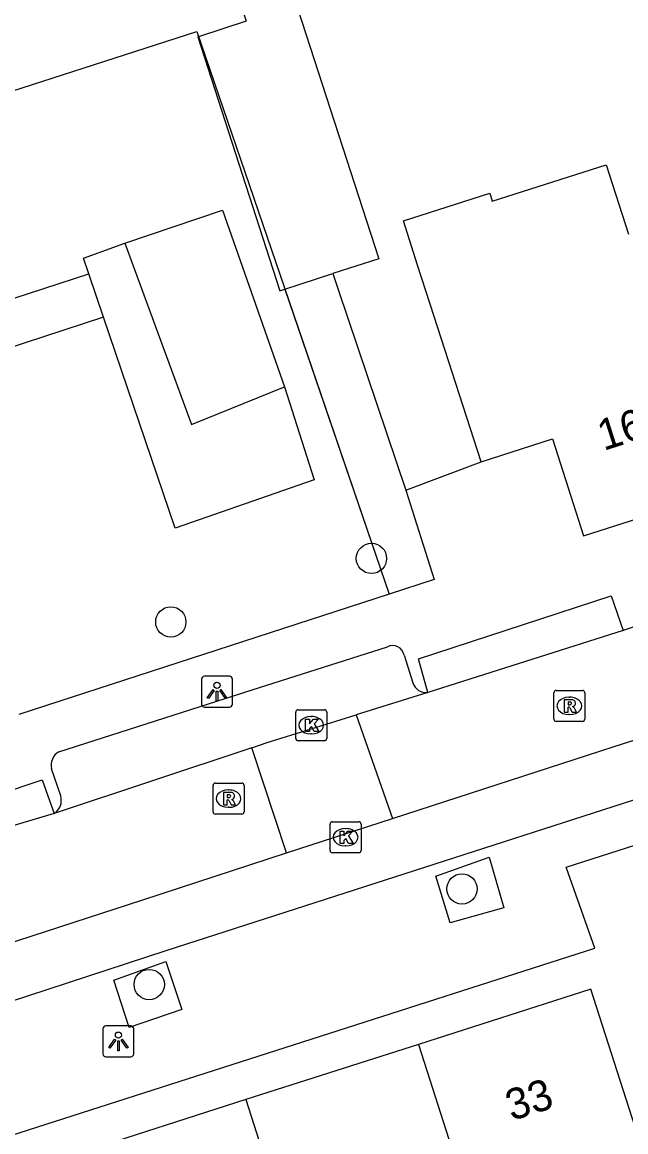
# Model space of a CAD drawing. Extents: x 159718 to 160783, y 383290 to 384030.
# Drawn here: x 160060.55 to 160080.05, y 383542.1 to 383577.91 of the extents above; entities that cross this region are included whole.
import ezdxf

# ---------------------------------------------------------------- set-up
doc = ezdxf.new("R2010")
doc.units = 0
for name, color, linetype in [('IMGEO_Boom', 7, 'Continuous'), ('IMGEO_Grasland_overig', 7, 'Continuous'), ('IMGEO_Hek', 7, 'Continuous'), ('IMGEO_Kolk', 7, 'Continuous'), ('IMGEO_Lichtpunt', 7, 'Continuous'), ('IMGEO_Pand', 7, 'Continuous'), ('IMGEO_Pand_nummerreeks', 7, 'Continuous'), ('IMGEO_Rijbaan_lokaal_open', 7, 'Continuous'), ('IMGEO_Rioolput', 7, 'Continuous'), ('IMGEO_Voetpad_open', 7, 'Continuous')]:
    doc.layers.add(name, color=color, linetype=linetype)

msp = doc.modelspace()

# ---------------------------------------------------------------- linework, layer by layer
at = {"layer": 'IMGEO_Boom'}
for centre in [(160071.832, 383560.604), (160065.349, 383558.553), (160074.758, 383549.937), (160064.651, 383546.851)]:
    msp.add_circle(centre, 0.489, dxfattribs=at)
at = {"layer": 'IMGEO_Grasland_overig'}
for points in [[(160062.702, 383569.786), (160062.527, 383570.3), (160063.864, 383570.778)], [(160069.022, 383566.144), (160069.986, 383563.144), (160065.487, 383561.579), (160063.177, 383568.386)]]:
    msp.add_lwpolyline(points, dxfattribs=at)
at = {"layer": 'IMGEO_Hek'}
for points in [[(160066.188, 383577.609), (160069.019, 383569.335)], [(160069.019, 383569.335), (160072.402, 383559.445)]]:
    msp.add_lwpolyline(points, dxfattribs=at)
at = {"layer": 'IMGEO_Kolk'}
for p, q in [((160069.385, 383554.794), (160069.385, 383555.646)), ((160069.46, 383555.72), (160070.312, 383555.72)), ((160069.873, 383555.5), (160069.898, 383555.5)), ((160070.386, 383555.646), (160070.386, 383554.794)), ((160070.312, 383554.72), (160069.46, 383554.72)), ((160069.896, 383554.94), (160069.871, 383554.94)), ((160070.495, 383551.178), (160070.495, 383552.03)), ((160070.57, 383552.104), (160071.422, 383552.104)), ((160070.983, 383551.884), (160071.008, 383551.884)), ((160071.496, 383552.03), (160071.496, 383551.178)), ((160071.006, 383551.324), (160070.981, 383551.324)), ((160071.422, 383551.104), (160070.57, 383551.104))]:
    msp.add_line(p, q, dxfattribs=at)
for points in [[(160069.385, 383554.794), (160069.385, 383555.646)], [(160069.46, 383555.72), (160070.312, 383555.72)], [(160069.706, 383555.42), (160069.829, 383555.42), (160069.829, 383555.269), (160069.959, 383555.42), (160070.123, 383555.42), (160069.977, 383555.269), (160070.13, 383555.02), (160069.978, 383555.02), (160069.893, 383555.184), (160069.829, 383555.117), (160069.829, 383555.02), (160069.706, 383555.02), (160069.706, 383555.42)], [(160070.386, 383555.646), (160070.386, 383554.794)], [(160070.312, 383554.72), (160069.46, 383554.72)], [(160070.495, 383551.178), (160070.495, 383552.03)], [(160070.57, 383552.104), (160071.422, 383552.104)], [(160071.496, 383552.03), (160071.496, 383551.178)], [(160070.816, 383551.804), (160070.939, 383551.804), (160070.939, 383551.653), (160071.069, 383551.804), (160071.233, 383551.804), (160071.087, 383551.653), (160071.24, 383551.404), (160071.088, 383551.404), (160071.003, 383551.568), (160070.939, 383551.501), (160070.939, 383551.404), (160070.816, 383551.404), (160070.816, 383551.804)], [(160071.422, 383551.104), (160070.57, 383551.104)]]:
    msp.add_lwpolyline(points, dxfattribs=at)
for centre, start, end in [((160069.462, 383555.644), 91.552, 178.448), ((160069.462, 383555.644), 91.552, 178.448), ((160070.31, 383555.644), 1.552, 88.448), ((160070.31, 383555.644), 1.552, 88.448), ((160069.462, 383554.796), 181.552, 268.448), ((160069.462, 383554.796), 181.552, 268.448), ((160070.31, 383554.796), 271.552, 358.448), ((160070.31, 383554.796), 271.552, 358.448), ((160070.572, 383552.028), 91.552, 178.448), ((160070.572, 383552.028), 91.552, 178.448), ((160071.42, 383552.028), 1.552, 88.448), ((160071.42, 383552.028), 1.552, 88.448), ((160070.572, 383551.18), 181.552, 268.448), ((160070.572, 383551.18), 181.552, 268.448), ((160071.42, 383551.18), 271.552, 358.448), ((160071.42, 383551.18), 271.552, 358.448)]:
    msp.add_arc(centre, 0.0765, start, end, dxfattribs=at)
for centre, major_axis, ratio, start_param, end_param in [((160069.872, 383555.22), (-0.387, 0.002), 0.722429, 4.712389, 7.853982), ((160069.897, 383555.22), (-0.39, 0.002), 0.717154, 1.570796, 4.712389), ((160070.982, 383551.604), (-0.387, 0.002), 0.722429, 4.712389, 7.853982), ((160071.007, 383551.604), (-0.39, 0.002), 0.717154, 1.570796, 4.712389)]:
    msp.add_ellipse(centre, major_axis=major_axis, ratio=ratio, start_param=start_param, end_param=end_param, dxfattribs=at)
at = {"layer": 'IMGEO_Lichtpunt'}
for p, q in [((160066.342, 383556.707), (160066.342, 383555.9)), ((160066.342, 383556.707), (160066.342, 383555.9)), ((160067.244, 383556.802), (160066.436, 383556.802)), ((160067.244, 383556.802), (160066.436, 383556.802)), ((160067.338, 383555.9), (160067.338, 383556.707)), ((160067.338, 383555.9), (160067.338, 383556.707)), ((160066.436, 383555.806), (160067.244, 383555.806)), ((160066.436, 383555.806), (160067.244, 383555.806)), ((160063.158, 383545.419), (160063.158, 383544.612)), ((160063.158, 383545.419), (160063.158, 383544.612)), ((160064.06, 383545.514), (160063.252, 383545.514)), ((160064.06, 383545.514), (160063.252, 383545.514)), ((160064.154, 383544.612), (160064.154, 383545.419)), ((160064.154, 383544.612), (160064.154, 383545.419)), ((160063.252, 383544.518), (160064.06, 383544.518)), ((160063.252, 383544.518), (160064.06, 383544.518))]:
    msp.add_line(p, q, dxfattribs=at)
for points in [[(160066.716, 383556.371), (160066.755, 383556.343), (160066.567, 383556.081), (160066.529, 383556.108), (160066.716, 383556.371)], [(160066.818, 383556.323), (160066.865, 383556.323), (160066.865, 383556.001), (160066.818, 383556.001), (160066.818, 383556.323)], [(160066.928, 383556.343), (160066.966, 383556.37), (160067.153, 383556.108), (160067.114, 383556.08), (160066.928, 383556.343)], [(160063.532, 383545.083), (160063.571, 383545.055), (160063.383, 383544.793), (160063.345, 383544.82), (160063.532, 383545.083)], [(160063.634, 383545.035), (160063.681, 383545.035), (160063.681, 383544.713), (160063.634, 383544.713), (160063.634, 383545.035)], [(160063.744, 383545.055), (160063.782, 383545.082), (160063.969, 383544.82), (160063.93, 383544.792), (160063.744, 383545.055)]]:
    msp.add_lwpolyline(points, dxfattribs=at)
for centre in [(160066.841, 383556.505), (160063.657, 383545.217)]:
    msp.add_circle(centre, 0.0994, dxfattribs=at)
for centre, start, end in [((160066.436, 383556.707), 90, 180), ((160066.436, 383556.707), 90, 180), ((160067.244, 383556.707), 0, 90), ((160067.244, 383556.707), 0, 90), ((160066.436, 383555.9), 180, 270), ((160066.436, 383555.9), 180, 270), ((160067.244, 383555.9), 270, 0), ((160067.244, 383555.9), 270, 360), ((160063.252, 383545.419), 90, 180), ((160063.252, 383545.419), 90, 180), ((160064.06, 383545.419), 0, 90), ((160064.06, 383545.419), 0, 90), ((160063.252, 383544.612), 180, 270), ((160063.252, 383544.612), 180, 270), ((160064.06, 383544.612), 270, 0), ((160064.06, 383544.612), 270, 360)]:
    msp.add_arc(centre, 0.0946, start, end, dxfattribs=at)
at = {"layer": 'IMGEO_Pand'}
for points in [[(160069.212, 383578.705), (160069.327, 383578.742), (160072.068, 383570.277), (160070.582, 383569.796)], [(160067.693, 383578.213), (160067.782, 383577.939), (160066.245, 383577.442)], [(160066.245, 383577.442), (160066.221, 383577.434), (160068.874, 383569.242), (160069.033, 383569.294)], [(160075.38, 383563.726), (160073.853, 383568.407), (160073.321, 383570.07), (160072.865, 383571.496), (160075.653, 383572.388), (160075.735, 383572.131), (160079.413, 383573.308), (160080.131, 383571.064)], [(160063.864, 383570.778), (160067.023, 383571.841), (160069.022, 383566.144)], [(160063.864, 383570.778), (160066.013, 383564.93), (160069.022, 383566.144)], [(160069.033, 383569.294), (160070.582, 383569.796)], [(160075.38, 383563.726), (160077.685, 383564.462), (160078.686, 383561.328), (160083.238, 383562.781)], [(160075.835, 383537.157), (160081.409, 383538.942), (160080.447, 383541.944), (160078.922, 383546.705), (160073.349, 383544.92)], [(160073.349, 383544.92), (160067.778, 383543.135)], [(160073.349, 383544.92), (160075.835, 383537.157)], [(160067.778, 383543.135), (160062.288, 383541.377), (160062.699, 383540.092)], [(160067.778, 383543.135), (160070.266, 383535.373)]]:
    msp.add_lwpolyline(points, dxfattribs=at)
at = {"layer": 'IMGEO_Rijbaan_lokaal_open'}
for points in [[(160072.512, 383552.212), (160079.668, 383554.538), (160095.796, 383559.685)], [(160081.647, 383558.841), (160079.969, 383558.273)], [(160079.969, 383558.273), (160073.655, 383556.279)], [(160073.655, 383556.279), (160071.339, 383555.556)], [(160067.967, 383554.494), (160068.43, 383554.648), (160071.339, 383555.556)], [(160071.339, 383555.556), (160072.512, 383552.212)], [(160067.967, 383554.494), (160061.581, 383552.368)], [(160069.082, 383551.097), (160067.967, 383554.494)], [(160061.581, 383552.368), (160057.16, 383551.056)], [(160069.082, 383551.097), (160072.512, 383552.212)], [(160035.725, 383540.291), (160042.026, 383542.301), (160064.442, 383549.589), (160069.082, 383551.097)]]:
    msp.add_lwpolyline(points, dxfattribs=at)
at = {"layer": 'IMGEO_Rioolput'}
for p, q in [((160077.725, 383555.418), (160077.725, 383556.27)), ((160077.8, 383556.344), (160078.652, 383556.344)), ((160078.213, 383556.124), (160078.238, 383556.124)), ((160078.726, 383556.27), (160078.726, 383555.418)), ((160078.236, 383555.564), (160078.211, 383555.564)), ((160078.652, 383555.344), (160077.8, 383555.344)), ((160066.714, 383552.425), (160066.714, 383553.277)), ((160066.789, 383553.351), (160067.641, 383553.351)), ((160067.715, 383553.277), (160067.715, 383552.425)), ((160067.202, 383553.131), (160067.227, 383553.131)), ((160067.225, 383552.571), (160067.2, 383552.571)), ((160067.641, 383552.351), (160066.789, 383552.351))]:
    msp.add_line(p, q, dxfattribs=at)
for points in [[(160077.725, 383555.418), (160077.725, 383556.27)], [(160077.8, 383556.344), (160078.652, 383556.344)], [(160078.726, 383556.27), (160078.726, 383555.418)], [(160078.314, 383556.042), (160078.062, 383556.044), (160078.062, 383555.644)], [(160078.062, 383555.644), (160078.186, 383555.644), (160078.186, 383555.806), (160078.197, 383555.806)], [(160078.24, 383555.963), (160078.186, 383555.963), (160078.186, 383555.882)], [(160078.186, 383555.882), (160078.238, 383555.882)], [(160078.244, 383555.777), (160078.315, 383555.644), (160078.455, 383555.644), (160078.39, 383555.77)], [(160078.652, 383555.344), (160077.8, 383555.344)], [(160066.714, 383552.425), (160066.714, 383553.277)], [(160066.789, 383553.351), (160067.641, 383553.351)], [(160067.715, 383553.277), (160067.715, 383552.425)], [(160067.303, 383553.049), (160067.051, 383553.051), (160067.051, 383552.651)], [(160067.229, 383552.97), (160067.175, 383552.97), (160067.175, 383552.889)], [(160067.051, 383552.651), (160067.175, 383552.651), (160067.175, 383552.813), (160067.186, 383552.813)], [(160067.175, 383552.889), (160067.227, 383552.889)], [(160067.233, 383552.784), (160067.304, 383552.651), (160067.444, 383552.651), (160067.379, 383552.777)], [(160067.641, 383552.351), (160066.789, 383552.351)]]:
    msp.add_lwpolyline(points, dxfattribs=at)
for centre, radius, start, end in [((160077.802, 383556.268), 0.0765, 91.552, 178.448), ((160077.802, 383556.268), 0.0765, 91.552, 178.448), ((160078.65, 383556.268), 0.0765, 1.552, 88.448), ((160078.65, 383556.268), 0.0765, 1.552, 88.448), ((160078.196, 383555.753), 0.0533, 26.0293, 88.6989), ((160078.222, 383556.071), 0.19, 274.7715, 282.9687), ((160078.246, 383555.867), 0.0964, 77.0061, 93.1865), ((160078.26, 383555.924), 0.0378, 276.6634, 79.6772), ((160078.313, 383555.932), 0.109, 350.3612, 89.416), ((160078.311, 383555.932), 0.112, 277.5842, 350.9817), ((160078.295, 383555.717), 0.108, 29.5134, 73.7905), ((160077.802, 383555.42), 0.0765, 181.552, 268.448), ((160077.802, 383555.42), 0.0765, 181.552, 268.448), ((160078.65, 383555.42), 0.0765, 271.552, 358.448), ((160078.65, 383555.42), 0.0765, 271.552, 358.448), ((160066.791, 383553.275), 0.0765, 91.552, 178.448), ((160066.791, 383553.275), 0.0765, 91.552, 178.448), ((160067.639, 383553.275), 0.0765, 1.552, 88.448), ((160067.639, 383553.275), 0.0765, 1.552, 88.448), ((160067.235, 383552.874), 0.0964, 77.0061, 93.1865), ((160067.249, 383552.931), 0.0378, 276.6634, 79.6772), ((160067.302, 383552.939), 0.109, 350.3612, 89.416), ((160067.3, 383552.939), 0.112, 277.5842, 350.9817), ((160067.185, 383552.76), 0.0533, 26.0293, 88.6989), ((160067.211, 383553.078), 0.19, 274.7715, 282.9687), ((160067.284, 383552.724), 0.108, 29.5134, 73.7905), ((160066.791, 383552.427), 0.0765, 181.552, 268.448), ((160066.791, 383552.427), 0.0765, 181.552, 268.448), ((160067.639, 383552.427), 0.0765, 271.552, 358.448), ((160067.639, 383552.427), 0.0765, 271.552, 358.448)]:
    msp.add_arc(centre, radius, start, end, dxfattribs=at)
for centre, major_axis, ratio, start_param, end_param in [((160078.212, 383555.844), (-0.387, 0.002), 0.722429, 4.712389, 7.853982), ((160078.237, 383555.844), (-0.39, 0.002), 0.717154, 1.570796, 4.712389), ((160067.201, 383552.851), (-0.387, 0.002), 0.722429, 4.712389, 7.853982), ((160067.226, 383552.851), (-0.39, 0.002), 0.717154, 1.570796, 4.712389)]:
    msp.add_ellipse(centre, major_axis=major_axis, ratio=ratio, start_param=start_param, end_param=end_param, dxfattribs=at)
at = {"layer": 'IMGEO_Voetpad_open'}
for points in [[(160060.218, 383575.684), (160066.188, 383577.609), (160066.245, 383577.442)], [(160055.537, 383559.797), (160054.533, 383562.98), (160052.552, 383562.321), (160050.748, 383567.999), (160056.271, 383569.779), (160056.91, 383567.907), (160062.702, 383569.786)], [(160063.177, 383568.386), (160062.702, 383569.786)], [(160070.582, 383569.796), (160070.766, 383569.252), (160072.944, 383562.805)], [(160069.033, 383569.294), (160072.402, 383559.445)], [(160063.177, 383568.386), (160057.346, 383566.488), (160058.085, 383564.095), (160056.16, 383563.523), (160057.17, 383560.396)], [(160072.944, 383562.805), (160075.38, 383563.726)], [(160072.944, 383562.805), (160073.862, 383559.927), (160072.402, 383559.445)], [(160072.402, 383559.445), (160060.438, 383555.567)], [(160073.655, 383556.279), (160073.351, 383557.368), (160079.579, 383559.401), (160079.969, 383558.273)], [(160095.58, 383557.751), (160079.967, 383552.694), (160065.185, 383547.935), (160042.339, 383540.466), (160037.012, 383538.807)], [(160061.732, 383554.366), (160067.975, 383556.367), (160072.346, 383557.754)], [(160072.887, 383557.483), (160073.167, 383556.587)], [(160061.792, 383552.936), (160061.496, 383553.812)], [(160057.16, 383551.056), (160056.821, 383551.994), (160061.197, 383553.457), (160061.38, 383552.942), (160061.581, 383552.368)], [(160033.881, 383533.551), (160079.052, 383548.02), (160078.122, 383550.634), (160081.748, 383551.798)], [(160076.108, 383549.326), (160074.375, 383548.839), (160073.907, 383550.353), (160075.635, 383550.961), (160076.108, 383549.326)], [(160065.701, 383546.041), (160064.009, 383545.464), (160063.504, 383546.989), (160065.186, 383547.592), (160065.701, 383546.041)]]:
    msp.add_lwpolyline(points, dxfattribs=at)
for centre, radius, start, end in [((160072.512, 383557.41), 0.382, 11.0025, 115.7827), ((160073.591, 383556.719), 0.444, 197.2514, 278.2327), ((160061.987, 383553.93), 0.505, 120.3433, 193.5094), ((160061.3, 383552.796), 0.512, 303.3194, 15.9227)]:
    msp.add_arc(centre, radius, start, end, dxfattribs=at)

# ---------------------------------------------------------------- texts
at = {"layer": 'IMGEO_Pand_nummerreeks'}
for s, rotation, p in [('16', 17.7388, (160079.333, 383564.071)), ('33', 17.7607, (160076.363, 383542.441))]:
    msp.add_text(s, height=1, rotation=rotation, dxfattribs=at).set_placement(p)

doc.saveas('drawing.dxf')
